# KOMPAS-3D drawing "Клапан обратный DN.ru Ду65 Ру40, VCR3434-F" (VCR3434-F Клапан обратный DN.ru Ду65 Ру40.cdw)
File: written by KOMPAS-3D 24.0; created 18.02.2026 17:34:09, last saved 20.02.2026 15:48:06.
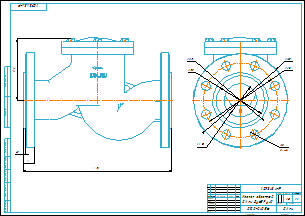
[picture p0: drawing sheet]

Document properties: art: D100-04056; Автор: R2D2; Форматы листов документа: A2; Полное имя файла: VCR3434-F Клапан обратный DN.ru Ду65 Ру40.m3d; Масса: 16; Наименование: Клапан обратный DN.ru Ду65 Ру40; Количество листов документа: 1; Примечание: D100-04056

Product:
- Part/product: Клапан обратный DN.ru Ду65 Ру40  | designation VCR3434-F
    Масса: 16
    Раздел спецификации: Прочие изделия
    Примечание: D100-04056
    additional columns: D100-04056

Views: Вид 1, Спереди
Referenced files in E:\Работа\Зайцев\VCR3434-F Клапан обратный DN.ru Ду15-300\DN65\: VCR3434-F Клапан обратный DN.ru Ду65 Ру40.m3d
Referenced files in E:\Работа\Зайцев\Для компаса\: чертеж DN.ru А3.cdt
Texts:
  Диаметральный размер
  VCR3434-F
  чертеж DN.ru А3.cdt
  Клапан обратный
  DN.ru Ду65 Ру40
  prop
  Клапан обратный DN.ru Ду65 Ру40
  VCR3434-F Клапан обратный DN.ru Ду65 Ру40
Dimensions and other numbers on the sheet: 0; 3; 2; 4; 185; 145; 18; 8 отв.; 65; 95; 109; 1:1; 1; 16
